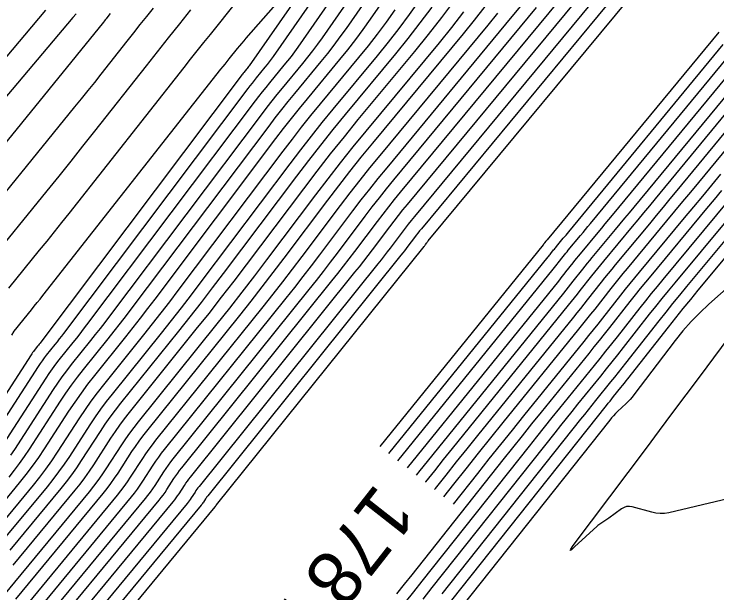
# Model space of a CAD drawing. Extents: x 7585033 to 7595090, y 547091 to 553471.
# Drawn here: x 7587423.4 to 7587504.7, y 548104.7 to 548171.7 of the extents above; entities that cross this region are included whole.
import ezdxf

# ---------------------------------------------------------------- set-up
doc = ezdxf.new("R2010")
doc.units = 0
for name, color, linetype in [('E_TERR_DSPLAY_GeneralTx', 7, 'Continuous'), ('E_TERR_DSPLAY_MajContour', 7, 'Continuous'), ('E_TERR_DSPLAY_MinContour', 7, 'Continuous')]:
    doc.layers.add(name, color=color, linetype=linetype)

msp = doc.modelspace()

# ---------------------------------------------------------------- linework, layer by layer
at = {"layer": 'E_TERR_DSPLAY_MajContour'}
for points in [[(7587476.027, 548193.439), (7587458.998, 548168.938), (7587458.458, 548168.179), (7587457.903, 548167.432), (7587457.332, 548166.696), (7587456.746, 548165.973), (7587454.369, 548163.103), (7587453.779, 548162.382), (7587453.198, 548161.654), (7587452.625, 548160.92), (7587452.061, 548160.178), (7587434.409, 548136.713), (7587433.871, 548136.003), (7587433.327, 548135.297), (7587432.777, 548134.595), (7587432.222, 548133.898), (7587429.99, 548131.118), (7587429.441, 548130.416), (7587428.911, 548129.701), (7587428.399, 548128.973), (7587427.905, 548128.231), (7587423.412, 548121.299), (7587422.979, 548120.652)], [(7587424.781, 548088.19), (7587446.629, 548114.663), (7587446.644, 548114.681), (7587446.657, 548114.699), (7587446.671, 548114.718), (7587446.683, 548114.737), (7587446.733, 548114.813), (7587446.746, 548114.832), (7587446.759, 548114.851), (7587446.772, 548114.869), (7587446.786, 548114.887), (7587470.788, 548144.79), (7587470.83, 548144.843), (7587470.872, 548144.896), (7587470.913, 548144.95), (7587470.954, 548145.004), (7587471.116, 548145.219), (7587471.157, 548145.273), (7587471.199, 548145.326), (7587471.241, 548145.379), (7587471.284, 548145.431), (7587497.838, 548177.502)], [(7587424.177, 548096.08), (7587440.152, 548115.436), (7587440.389, 548115.732), (7587440.617, 548116.034), (7587440.837, 548116.343), (7587441.048, 548116.659), (7587441.874, 548117.933), (7587442.084, 548118.249), (7587442.303, 548118.559), (7587442.529, 548118.864), (7587442.762, 548119.163), (7587460.134, 548140.806), (7587460.808, 548141.652), (7587461.476, 548142.504), (7587462.136, 548143.361), (7587462.79, 548144.223), (7587465.392, 548147.683), (7587466.048, 548148.544), (7587466.713, 548149.397), (7587467.389, 548150.242), (7587468.074, 548151.079), (7587486.588, 548173.439)], [(7587470.227, 548173.26), (7587469.064, 548171.623), (7587467.867, 548170.012), (7587466.636, 548168.426), (7587465.372, 548166.866), (7587460.247, 548160.677), (7587458.975, 548159.122), (7587457.722, 548157.553), (7587456.487, 548155.97), (7587455.27, 548154.372), (7587444.973, 548140.683), (7587443.841, 548139.191), (7587442.698, 548137.708), (7587441.544, 548136.235), (7587440.377, 548134.77), (7587434.714, 548127.714), (7587434.041, 548126.853), (7587433.39, 548125.976), (7587432.762, 548125.083), (7587432.156, 548124.173), (7587429.777, 548120.503), (7587429.17, 548119.595), (7587428.537, 548118.705), (7587427.879, 548117.834), (7587427.196, 548116.981), (7587422.249, 548110.987)], [(7587417.379, 548144.906), (7587430.421, 548160.941), (7587431.186, 548161.884), (7587431.947, 548162.831), (7587432.703, 548163.781), (7587433.457, 548164.734), (7587436.461, 548168.553), (7587437.214, 548169.506), (7587437.969, 548170.457), (7587438.728, 548171.406), (7587439.489, 548172.353)], [(7587423.572, 548103.969), (7587433.674, 548116.209), (7587434.134, 548116.783), (7587434.577, 548117.37), (7587435.004, 548117.969), (7587435.413, 548118.581), (7587437.015, 548121.053), (7587437.423, 548121.666), (7587437.846, 548122.268), (7587438.285, 548122.858), (7587438.738, 548123.438), (7587449.48, 548136.822), (7587450.786, 548138.462), (7587452.079, 548140.112), (7587453.359, 548141.773), (7587454.626, 548143.443), (7587459.668, 548150.146), (7587460.938, 548151.814), (7587462.228, 548153.467), (7587463.536, 548155.105), (7587464.864, 548156.728), (7587475.337, 548169.376), (7587476.619, 548170.958), (7587477.866, 548172.565)], [(7587504.865, 548169.595), (7587485.019, 548145.548), (7587484.988, 548145.511), (7587484.957, 548145.473), (7587484.925, 548145.435), (7587484.894, 548145.398), (7587484.739, 548145.211), (7587484.723, 548145.191), (7587484.707, 548145.172), (7587484.691, 548145.152), (7587484.675, 548145.132), (7587484.612, 548145.052), (7587484.596, 548145.032), (7587484.58, 548145.012), (7587484.564, 548144.992), (7587484.548, 548144.972), (7587465.674, 548121.648)], [(7587506.989, 548163.82), (7587495.049, 548149.353), (7587494.51, 548148.701), (7587493.971, 548148.049), (7587493.431, 548147.398), (7587492.89, 548146.747), (7587490.207, 548143.522), (7587489.927, 548143.183), (7587489.649, 548142.842), (7587489.373, 548142.498), (7587489.1, 548142.153), (7587488.012, 548140.768), (7587487.74, 548140.423), (7587487.466, 548140.078), (7587487.191, 548139.734), (7587486.914, 548139.392), (7587471.162, 548119.926), (7587470.323, 548118.887), (7587469.886, 548118.343)], [(7587505.079, 548153.157), (7587504.032, 548151.891), (7587502.985, 548150.625), (7587501.936, 548149.36), (7587500.886, 548148.097), (7587495.675, 548141.834), (7587495.13, 548141.174), (7587494.591, 548140.512), (7587494.056, 548139.845), (7587493.525, 548139.174), (7587491.412, 548136.485), (7587490.883, 548135.814), (7587490.351, 548135.145), (7587489.817, 548134.477), (7587489.28, 548133.812), (7587482.305, 548125.192), (7587480.965, 548123.532), (7587479.63, 548121.869), (7587478.298, 548120.203), (7587476.97, 548118.534), (7587474.159, 548114.991)], [(7587511.355, 548152.42), (7587501.143, 548140.145), (7587500.334, 548139.166), (7587499.533, 548138.182), (7587498.738, 548137.192), (7587497.95, 548136.196), (7587494.099, 548131.294), (7587493.67, 548130.75), (7587493.24, 548130.209), (7587492.808, 548129.668), (7587492.373, 548129.13), (7587490.632, 548126.978), (7587490.197, 548126.439), (7587489.764, 548125.9), (7587489.332, 548125.359), (7587488.901, 548124.818), (7587472.855, 548104.593)]]:
    msp.add_lwpolyline(points, dxfattribs=at)
at = {"layer": 'E_TERR_DSPLAY_MinContour'}
for points in [[(7587419.922, 548121.222), (7587426.203, 548130.914), (7587426.425, 548131.248), (7587426.655, 548131.575), (7587426.894, 548131.897), (7587427.141, 548132.212), (7587428.144, 548133.462), (7587428.394, 548133.776), (7587428.641, 548134.091), (7587428.886, 548134.409), (7587429.128, 548134.728), (7587450.456, 548163.082), (7587450.694, 548163.394), (7587450.936, 548163.704), (7587451.181, 548164.011), (7587451.43, 548164.315), (7587452.433, 548165.526), (7587452.68, 548165.832), (7587452.921, 548166.142), (7587453.155, 548166.457), (7587453.383, 548166.777), (7587473.383, 548195.552)], [(7587474.705, 548194.496), (7587456.19, 548167.858), (7587455.807, 548167.318), (7587455.412, 548166.787), (7587455.006, 548166.264), (7587454.589, 548165.75), (7587452.9, 548163.709), (7587452.48, 548163.196), (7587452.067, 548162.679), (7587451.66, 548162.157), (7587451.259, 548161.63), (7587431.769, 548135.721), (7587431.378, 548135.206), (7587430.984, 548134.694), (7587430.585, 548134.186), (7587430.183, 548133.68), (7587428.565, 548131.665), (7587428.168, 548131.156), (7587427.783, 548130.638), (7587427.412, 548130.11), (7587427.054, 548129.573), (7587421.667, 548121.261)], [(7587422.798, 548118.119), (7587423.423, 548118.898), (7587424.024, 548119.694), (7587424.602, 548120.508), (7587425.158, 548121.338), (7587428.756, 548126.89), (7587429.385, 548127.835), (7587430.039, 548128.764), (7587430.715, 548129.676), (7587431.415, 548130.57), (7587434.261, 548134.116), (7587434.969, 548135.005), (7587435.67, 548135.9), (7587436.363, 548136.8), (7587437.05, 548137.706), (7587452.863, 548158.727), (7587453.59, 548159.682), (7587454.329, 548160.629), (7587455.078, 548161.567), (7587455.839, 548162.496), (7587458.902, 548166.196), (7587459.658, 548167.129), (7587460.394, 548168.077), (7587461.11, 548169.04), (7587461.805, 548170.018), (7587477.349, 548192.383)], [(7587420.918, 548113.686), (7587424.024, 548117.448), (7587424.786, 548118.399), (7587425.52, 548119.371), (7587426.226, 548120.363), (7587426.903, 548121.377), (7587429.726, 548125.733), (7587430.431, 548126.791), (7587431.162, 548127.83), (7587431.919, 548128.85), (7587432.702, 548129.852), (7587436.3, 548134.334), (7587437.16, 548135.415), (7587438.013, 548136.503), (7587438.856, 548137.597), (7587439.691, 548138.698), (7587453.665, 548157.275), (7587454.556, 548158.445), (7587455.46, 548159.604), (7587456.377, 548160.752), (7587457.308, 548161.89), (7587461.059, 548166.419), (7587461.984, 548167.561), (7587462.885, 548168.722), (7587463.761, 548169.901), (7587464.612, 548171.099), (7587478.671, 548191.326)], [(7587423.109, 548134.535), (7587423.407, 548134.974), (7587423.719, 548135.402), (7587424.047, 548135.819), (7587425.388, 548137.468), (7587425.722, 548137.881), (7587426.055, 548138.295), (7587426.386, 548138.711), (7587426.716, 548139.128), (7587447.305, 548165.294), (7587447.544, 548165.596), (7587447.783, 548165.898), (7587448.024, 548166.199), (7587448.265, 548166.499), (7587449.233, 548167.699), (7587449.476, 548167.997), (7587449.723, 548168.293), (7587449.972, 548168.587), (7587450.225, 548168.878), (7587459.383, 548179.328)], [(7587459.815, 548178.99), (7587450.575, 548165.697), (7587450.504, 548165.596), (7587450.43, 548165.497), (7587450.354, 548165.399), (7587450.276, 548165.303), (7587449.961, 548164.922), (7587449.882, 548164.826), (7587449.805, 548164.729), (7587449.729, 548164.632), (7587449.654, 548164.533), (7587426.487, 548133.736), (7587426.393, 548133.612), (7587426.298, 548133.489), (7587426.202, 548133.366), (7587426.105, 548133.245), (7587425.716, 548132.759), (7587425.62, 548132.637), (7587425.527, 548132.512), (7587425.438, 548132.385), (7587425.352, 548132.256), (7587418.177, 548121.184)], [(7587495.026, 548176.486), (7587470.481, 548146.843), (7587470.278, 548146.595), (7587470.078, 548146.344), (7587469.88, 548146.091), (7587469.685, 548145.835), (7587468.913, 548144.809), (7587468.719, 548144.553), (7587468.523, 548144.298), (7587468.325, 548144.045), (7587468.125, 548143.794), (7587445.78, 548115.956), (7587445.711, 548115.868), (7587445.645, 548115.778), (7587445.58, 548115.686), (7587445.518, 548115.593), (7587445.275, 548115.217), (7587445.212, 548115.124), (7587445.147, 548115.033), (7587445.08, 548114.944), (7587445.01, 548114.856), (7587424.63, 548090.163)], [(7587492.213, 548175.471), (7587469.679, 548148.255), (7587469.315, 548147.811), (7587468.956, 548147.362), (7587468.603, 548146.908), (7587468.254, 548146.451), (7587466.872, 548144.614), (7587466.525, 548144.156), (7587466.174, 548143.7), (7587465.819, 548143.248), (7587465.461, 548142.798), (7587444.774, 548117.025), (7587444.65, 548116.866), (7587444.531, 548116.705), (7587444.415, 548116.541), (7587444.304, 548116.373), (7587443.866, 548115.698), (7587443.754, 548115.53), (7587443.637, 548115.367), (7587443.516, 548115.206), (7587443.391, 548115.049), (7587424.479, 548092.135)], [(7587424.328, 548094.107), (7587441.771, 548115.243), (7587441.953, 548115.469), (7587442.127, 548115.701), (7587442.296, 548115.937), (7587442.457, 548116.178), (7587443.089, 548117.153), (7587443.25, 548117.395), (7587443.417, 548117.632), (7587443.589, 548117.865), (7587443.768, 548118.094), (7587462.798, 548141.802), (7587463.314, 548142.45), (7587463.825, 548143.102), (7587464.331, 548143.758), (7587464.831, 548144.418), (7587466.823, 548147.067), (7587467.325, 548147.726), (7587467.835, 548148.379), (7587468.352, 548149.026), (7587468.876, 548149.667), (7587489.4, 548174.455)], [(7587449.119, 548173.135), (7587446.046, 548169.325), (7587445.279, 548168.372), (7587444.515, 548167.416), (7587443.753, 548166.457), (7587442.995, 548165.497), (7587429.717, 548148.622), (7587428.868, 548147.548), (7587428.015, 548146.477), (7587427.158, 548145.41), (7587426.296, 548144.346), (7587422.73, 548139.961)], [(7587423.27, 548107.914), (7587430.435, 548116.595), (7587431.007, 548117.308), (7587431.557, 548118.037), (7587432.087, 548118.782), (7587432.595, 548119.542), (7587434.585, 548122.613), (7587435.092, 548123.374), (7587435.618, 548124.122), (7587436.163, 548124.856), (7587436.726, 548125.576), (7587444.455, 548135.206), (7587445.927, 548137.054), (7587447.384, 548138.914), (7587448.827, 548140.785), (7587450.254, 548142.668), (7587456.874, 548151.468), (7587458.417, 548153.495), (7587459.984, 548155.503), (7587461.573, 548157.493), (7587463.186, 548159.464), (7587469.712, 548167.345), (7587471.302, 548169.307), (7587472.85, 548171.301), (7587474.355, 548173.327)], [(7587411.77, 548153.998), (7587425.447, 548170.208), (7587426.249, 548171.16), (7587427.049, 548172.114)], [(7587420.054, 548142.434), (7587427.204, 548151.223), (7587428.593, 548152.938), (7587429.975, 548154.659), (7587431.35, 548156.385), (7587432.718, 548158.116), (7587438.686, 548165.7), (7587439.963, 548167.319), (7587441.246, 548168.933), (7587442.533, 548170.544), (7587443.826, 548172.151)], [(7587467.42, 548172.179), (7587466.412, 548170.762), (7587465.376, 548169.367), (7587464.31, 548167.994), (7587463.215, 548166.643), (7587458.778, 548161.283), (7587457.676, 548159.937), (7587456.591, 548158.579), (7587455.521, 548157.207), (7587454.468, 548155.823), (7587442.332, 548139.69), (7587441.349, 548138.394), (7587440.355, 548137.105), (7587439.352, 548135.825), (7587438.339, 548134.552), (7587433.708, 548128.783), (7587432.98, 548127.852), (7587432.276, 548126.903), (7587431.596, 548125.937), (7587430.941, 548124.953), (7587428.368, 548120.984), (7587427.712, 548120.001), (7587427.027, 548119.039), (7587426.316, 548118.097), (7587425.577, 548117.175), (7587421.584, 548112.336)], [(7587475.358, 548171.933), (7587473.96, 548170.132), (7587472.524, 548168.361), (7587464.061, 548158.14), (7587462.573, 548156.321), (7587461.106, 548154.485), (7587459.661, 548152.632), (7587458.237, 548150.762), (7587452.585, 548143.248), (7587451.165, 548141.376), (7587449.73, 548139.514), (7587448.281, 548137.664), (7587446.817, 548135.825), (7587437.732, 548124.507), (7587437.224, 548123.857), (7587436.732, 548123.195), (7587436.258, 548122.52), (7587435.8, 548121.833), (7587434.004, 548119.061), (7587433.545, 548118.375), (7587433.067, 548117.704), (7587432.571, 548117.046), (7587432.054, 548116.402), (7587423.421, 548105.941), (7587422.367, 548104.643)], [(7587422.914, 548109.638), (7587428.816, 548116.788), (7587429.443, 548117.571), (7587430.047, 548118.371), (7587430.628, 548119.188), (7587431.186, 548120.023), (7587433.371, 548123.393), (7587433.927, 548124.229), (7587434.504, 548125.049), (7587435.102, 548125.854), (7587435.72, 548126.645), (7587442.416, 548134.988), (7587443.735, 548136.644), (7587445.041, 548138.311), (7587446.334, 548139.988), (7587447.614, 548141.675), (7587456.072, 548152.92), (7587457.452, 548154.732), (7587458.853, 548156.528), (7587460.274, 548158.308), (7587461.717, 548160.071), (7587467.528, 548167.089), (7587468.962, 548168.858), (7587470.358, 548170.657), (7587471.715, 548172.484)], [(7587481.935, 548172.608), (7587480.962, 548171.408), (7587466.469, 548153.904), (7587465.462, 548152.673), (7587464.47, 548151.432), (7587463.493, 548150.179), (7587462.53, 548148.914), (7587458.708, 548143.833), (7587457.748, 548142.567), (7587456.777, 548141.308), (7587455.797, 548140.057), (7587454.807, 548138.814), (7587440.75, 548121.3), (7587440.407, 548120.861), (7587440.074, 548120.413), (7587439.754, 548119.957), (7587439.444, 548119.493), (7587438.23, 548117.62), (7587437.92, 548117.156), (7587437.597, 548116.702), (7587437.262, 548116.257), (7587436.913, 548115.822), (7587423.875, 548100.024)], [(7587483.775, 548172.424), (7587467.271, 548152.492), (7587466.425, 548151.458), (7587465.592, 548150.414), (7587464.771, 548149.361), (7587463.961, 548148.299), (7587460.749, 548144.028), (7587459.942, 548142.964), (7587459.127, 548141.906), (7587458.303, 548140.855), (7587457.471, 548139.81), (7587441.756, 548120.232), (7587441.468, 548119.862), (7587441.188, 548119.486), (7587440.919, 548119.103), (7587440.659, 548118.713), (7587439.639, 548117.139), (7587439.379, 548116.75), (7587439.107, 548116.368), (7587438.825, 548115.995), (7587438.532, 548115.629), (7587424.026, 548098.052)], [(7587430.545, 548171.725), (7587430.176, 548171.287), (7587412.178, 548149.954)], [(7587434.498, 548171.738), (7587434.112, 548171.248), (7587434.016, 548171.125), (7587433.918, 548171.004), (7587433.821, 548170.882), (7587433.723, 548170.761), (7587414.704, 548147.379)], [(7587479.277, 548171.783), (7587478.15, 548170.392), (7587465.666, 548155.316), (7587464.499, 548153.889), (7587463.349, 548152.45), (7587462.216, 548150.997), (7587461.099, 548149.53), (7587456.667, 548143.638), (7587455.554, 548142.17), (7587454.428, 548140.71), (7587453.292, 548139.26), (7587452.144, 548137.818), (7587439.744, 548122.369), (7587439.346, 548121.86), (7587438.96, 548121.341), (7587438.588, 548120.812), (7587438.23, 548120.273), (7587436.822, 548118.1), (7587436.462, 548117.563), (7587436.087, 548117.036), (7587435.698, 548116.52), (7587435.293, 548116.015), (7587423.724, 548101.997)], [(7587466.726, 548120.822), (7587485.14, 548143.577), (7587485.221, 548143.677), (7587485.302, 548143.778), (7587485.382, 548143.879), (7587485.462, 548143.981), (7587485.781, 548144.387), (7587485.861, 548144.488), (7587485.942, 548144.589), (7587486.024, 548144.689), (7587486.106, 548144.789), (7587486.893, 548145.735), (7587487.052, 548145.926), (7587487.21, 548146.117), (7587487.368, 548146.308), (7587487.527, 548146.499), (7587505.396, 548168.151)], [(7587467.778, 548119.997), (7587485.731, 548142.182), (7587485.877, 548142.363), (7587486.023, 548142.545), (7587486.168, 548142.727), (7587486.312, 548142.91), (7587486.887, 548143.642), (7587487.032, 548143.825), (7587487.178, 548144.007), (7587487.325, 548144.187), (7587487.473, 548144.367), (7587488.892, 548146.072), (7587489.178, 548146.417), (7587489.464, 548146.761), (7587489.749, 548147.106), (7587490.034, 548147.451), (7587505.927, 548166.708)], [(7587506.458, 548165.264), (7587492.541, 548148.402), (7587492.13, 548147.903), (7587491.717, 548147.405), (7587491.304, 548146.907), (7587490.891, 548146.41), (7587488.84, 548143.944), (7587488.626, 548143.685), (7587488.413, 548143.424), (7587488.202, 548143.162), (7587487.994, 548142.898), (7587487.162, 548141.839), (7587486.954, 548141.575), (7587486.744, 548141.311), (7587486.534, 548141.049), (7587486.323, 548140.787), (7587468.831, 548119.171)], [(7587470.95, 548117.509), (7587470.992, 548117.561), (7587472.023, 548118.851), (7587473.057, 548120.139), (7587474.095, 548121.424), (7587487.506, 548137.997), (7587487.847, 548138.42), (7587488.187, 548138.845), (7587488.525, 548139.271), (7587488.862, 548139.698), (7587490.206, 548141.408), (7587490.544, 548141.835), (7587490.884, 548142.259), (7587491.228, 548142.681), (7587491.574, 548143.1), (7587494.889, 548147.085), (7587495.557, 548147.888), (7587496.224, 548148.693), (7587496.891, 548149.498), (7587497.556, 548150.304), (7587507.52, 548162.377)], [(7587472.019, 548116.67), (7587472.106, 548116.78), (7587473.331, 548118.32), (7587474.559, 548119.857), (7587475.791, 548121.391), (7587477.027, 548122.922), (7587488.097, 548136.602), (7587488.504, 548137.106), (7587488.908, 548137.611), (7587489.311, 548138.118), (7587489.712, 548138.627), (7587491.312, 548140.664), (7587491.714, 548141.172), (7587492.12, 548141.677), (7587492.529, 548142.179), (7587492.941, 548142.678), (7587496.888, 548147.422), (7587497.683, 548148.379), (7587498.478, 548149.337), (7587499.271, 548150.296), (7587500.064, 548151.255), (7587508.051, 548160.933)], [(7587473.089, 548115.831), (7587474.248, 548117.291), (7587475.669, 548119.079), (7587477.095, 548120.862), (7587478.525, 548122.643), (7587479.96, 548124.42), (7587488.689, 548135.207), (7587489.16, 548135.791), (7587489.63, 548136.378), (7587490.097, 548136.966), (7587490.562, 548137.556), (7587492.419, 548139.919), (7587492.885, 548140.508), (7587493.355, 548141.094), (7587493.829, 548141.677), (7587494.308, 548142.256), (7587498.887, 548147.76), (7587499.81, 548148.87), (7587500.731, 548149.981), (7587501.652, 548151.093), (7587502.571, 548152.206), (7587508.582, 548159.489)], [(7587474.007, 548103.856), (7587491.884, 548126.389), (7587492.09, 548126.648), (7587492.297, 548126.907), (7587492.505, 548127.166), (7587492.714, 548127.424), (7587493.548, 548128.456), (7587493.757, 548128.714), (7587493.964, 548128.973), (7587494.17, 548129.233), (7587494.376, 548129.493), (7587499.056, 548135.451), (7587499.909, 548136.528), (7587500.768, 548137.599), (7587501.635, 548138.664), (7587502.51, 548139.723), (7587513.973, 548153.502)], [(7587467.655, 548104.612), (7587468.528, 548105.706), (7587469.399, 548106.802), (7587479.953, 548120.105), (7587481.056, 548121.492), (7587482.163, 548122.877), (7587483.273, 548124.259), (7587484.387, 548125.639), (7587489.872, 548132.417), (7587490.474, 548133.163), (7587491.073, 548133.911), (7587491.669, 548134.662), (7587492.262, 548135.415), (7587494.631, 548138.43), (7587495.226, 548139.182), (7587495.826, 548139.929), (7587496.431, 548140.672), (7587497.042, 548141.411), (7587503.501, 548149.175), (7587504.371, 548150.221), (7587505.239, 548151.268)], [(7587508.737, 548151.338), (7587499.776, 548140.567), (7587499.033, 548139.668), (7587498.297, 548138.764), (7587497.567, 548137.855), (7587496.844, 548136.941), (7587493.822, 548133.094), (7587493.17, 548132.268), (7587492.516, 548131.444), (7587491.858, 548130.622), (7587491.198, 548129.803), (7587488.55, 548126.531), (7587487.889, 548125.713), (7587487.23, 548124.892), (7587486.573, 548124.07), (7587485.918, 548123.247), (7587471.703, 548105.329), (7587470.643, 548103.996)], [(7587506.119, 548150.257), (7587498.409, 548140.989), (7587497.732, 548140.17), (7587497.062, 548139.347), (7587496.397, 548138.518), (7587495.738, 548137.685), (7587493.112, 548134.344), (7587492.455, 548133.51), (7587491.794, 548132.678), (7587491.13, 548131.849), (7587490.463, 548131.022), (7587486.469, 548126.085), (7587485.581, 548124.986), (7587484.697, 548123.885), (7587483.815, 548122.781), (7587482.936, 548121.676), (7587470.551, 548106.066), (7587469.586, 548104.851), (7587468.618, 548103.638)], [(7587514.491, 548147.63), (7587503.722, 548138.101), (7587502.675, 548137.128), (7587501.68, 548136.108), (7587500.736, 548135.04), (7587499.844, 548133.924), (7587495.054, 548127.623), (7587494.845, 548127.359), (7587494.626, 548127.103), (7587494.396, 548126.856), (7587494.157, 548126.619), (7587493.18, 548125.685), (7587492.94, 548125.448), (7587492.709, 548125.202), (7587492.486, 548124.95), (7587492.272, 548124.689), (7587475.159, 548103.12)], [(7587514.505, 548117.647), (7587499.085, 548113.993), (7587498.592, 548113.908), (7587498.101, 548113.886), (7587497.611, 548113.928), (7587497.122, 548114.033), (7587494.868, 548114.666), (7587494.537, 548114.723), (7587494.221, 548114.704), (7587493.918, 548114.61), (7587493.628, 548114.44), (7587492.156, 548113.358), (7587492.045, 548113.277), (7587491.932, 548113.198), (7587491.818, 548113.121), (7587491.702, 548113.046), (7587491.238, 548112.749), (7587491.123, 548112.672), (7587491.013, 548112.591), (7587490.906, 548112.505), (7587490.803, 548112.414), (7587488.209, 548110.023), (7587487.849, 548109.711), (7587487.7, 548109.632), (7587487.763, 548109.788), (7587488.038, 548110.178), (7587496.5, 548121.464), (7587498.037, 548123.515), (7587499.57, 548125.568), (7587501.102, 548127.622), (7587502.631, 548129.678), (7587515.368, 548146.824)]]:
    msp.add_lwpolyline(points, dxfattribs=at)

# ---------------------------------------------------------------- texts
at = {"layer": 'E_TERR_DSPLAY_GeneralTx'}
msp.add_text('178 ft', height=6.3, rotation=231.88512, dxfattribs=at).set_placement((7587465.271, 548117.564))

doc.saveas('drawing.dxf')
